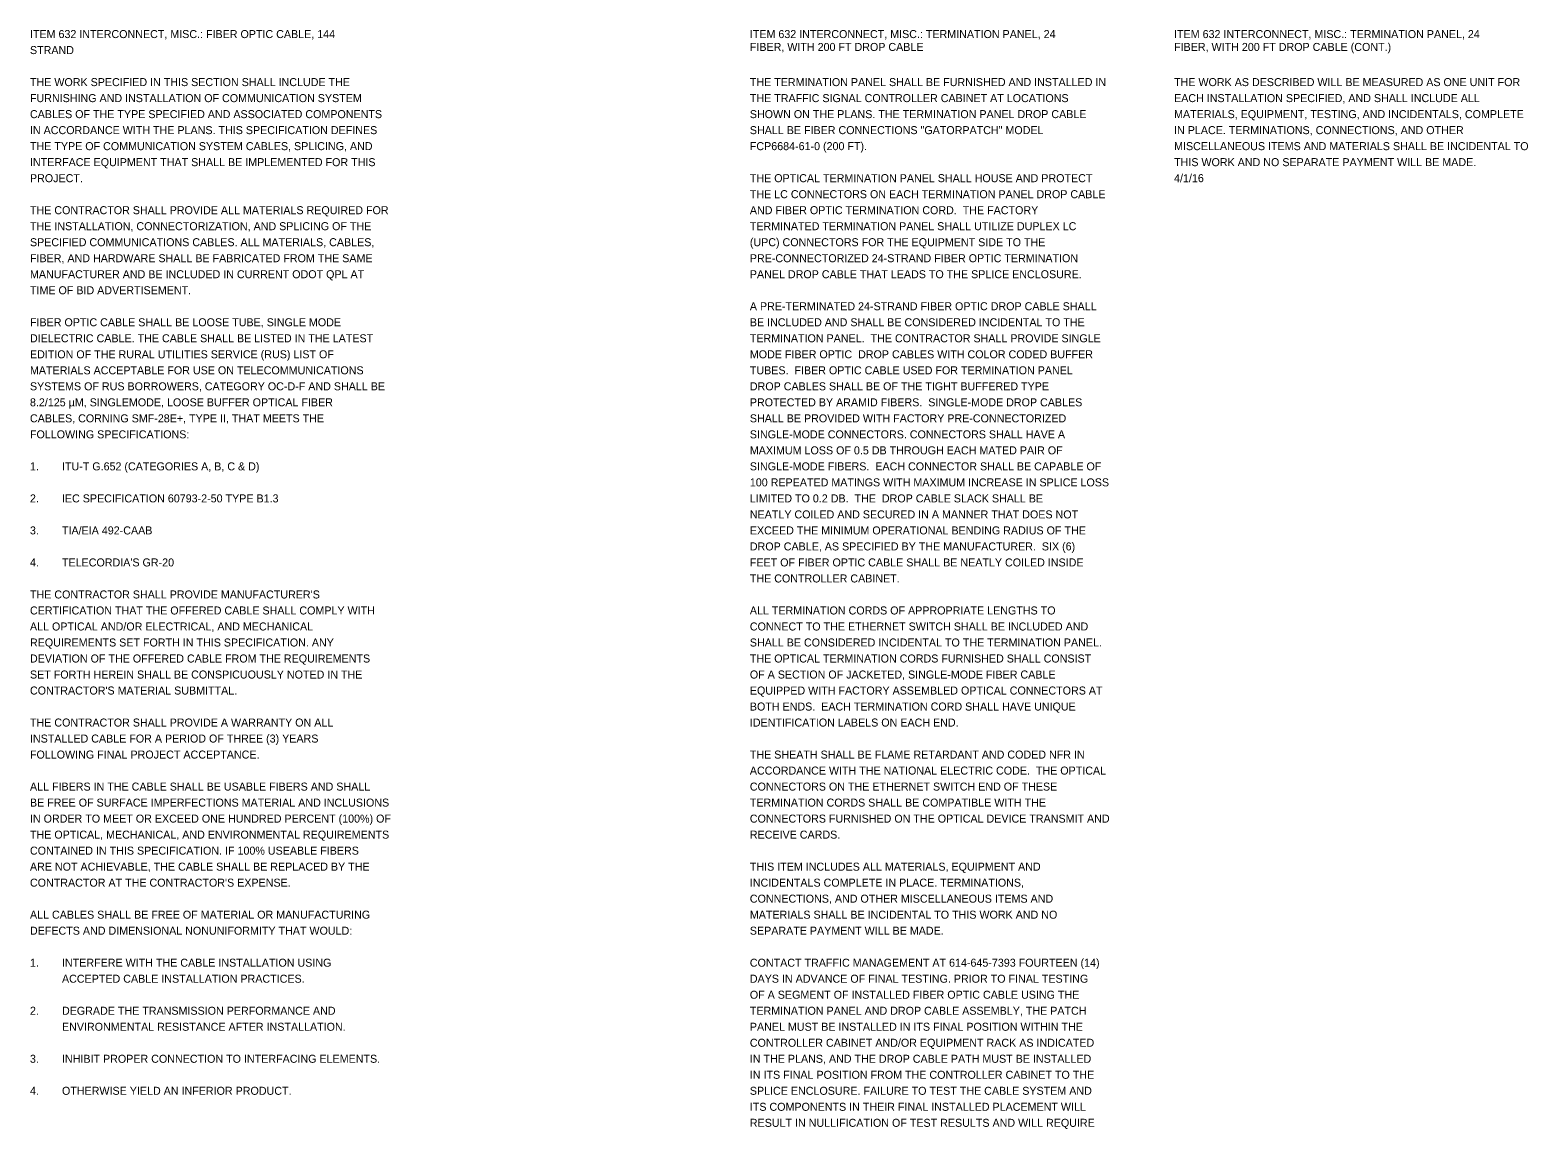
# Model space of a CAD drawing. Extents: x -39 to 75, y -25 to 14.
# Drawn here: x -39.19 to -12.99, y -5.45 to 13.77 of the extents above; entities that cross this region are included whole.
import ezdxf

# ---------------------------------------------------------------- set-up
doc = ezdxf.new("R2010")
doc.units = 0
doc.layers.add('SH_Data', color=7, linetype='Continuous')
doc.layers.add('SH_Text', color=7, linetype='Continuous')

msp = doc.modelspace()

# ---------------------------------------------------------------- texts
at = {"layer": 'SH_Data'}
for s, p in [('ITEM 632 INTERCONNECT, MISC.: FIBER OPTIC CABLE, 144 ', (-39.188, 13.632)), ('ITEM 632 INTERCONNECT, MISC.: TERMINATION PANEL, 24 ', (-26.597, 13.632)), ('ITEM 632 INTERCONNECT, MISC.: TERMINATION PANEL, 24 ', (-19.177, 13.632)), ('STRAND', (-39.188, 13.352)), ('FIBER, WITH 200 FT DROP CABLE', (-26.597, 13.407)), ('FIBER, WITH 200 FT DROP CABLE (CONT.)', (-19.177, 13.407))]:
    msp.add_text(s, height=0.14, dxfattribs=at).set_placement(p)
at = {"layer": 'SH_Text'}
for s, p in [('THE WORK SPECIFIED IN THIS SECTION SHALL INCLUDE THE ', (-39.188, 12.792)), ('FURNISHING AND INSTALLATION OF COMMUNICATION SYSTEM ', (-39.188, 12.512)), ('CABLES OF THE TYPE SPECIFIED AND ASSOCIATED COMPONENTS ', (-39.188, 12.232)), ('IN ACCORDANCE WITH THE PLANS. THIS SPECIFICATION DEFINES ', (-39.188, 11.952)), ('THE TYPE OF COMMUNICATION SYSTEM CABLES, SPLICING, AND ', (-39.188, 11.672)), ('INTERFACE EQUIPMENT THAT SHALL BE IMPLEMENTED FOR THIS ', (-39.188, 11.392)), ('PROJECT.', (-39.188, 11.112)), ('THE CONTRACTOR SHALL PROVIDE ALL MATERIALS REQUIRED FOR ', (-39.188, 10.552)), ('THE INSTALLATION, CONNECTORIZATION, AND SPLICING OF THE ', (-39.188, 10.272)), ('SPECIFIED COMMUNICATIONS CABLES. ALL MATERIALS, CABLES, ', (-39.188, 9.992)), ('FIBER, AND HARDWARE SHALL BE FABRICATED FROM THE SAME ', (-39.188, 9.712)), ('MANUFACTURER AND BE INCLUDED IN CURRENT ODOT QPL AT ', (-39.188, 9.432)), ('TIME OF BID ADVERTISEMENT.', (-39.188, 9.152)), ('FIBER OPTIC CABLE SHALL BE LOOSE TUBE, SINGLE MODE ', (-39.188, 8.592)), ('DIELECTRIC CABLE. THE CABLE SHALL BE LISTED IN THE LATEST ', (-39.188, 8.312)), ('EDITION OF THE RURAL UTILITIES SERVICE (RUS) LIST OF ', (-39.188, 8.032)), ('MATERIALS ACCEPTABLE FOR USE ON TELECOMMUNICATIONS ', (-39.188, 7.752)), ('SYSTEMS OF RUS BORROWERS, CATEGORY OC-D-F AND SHALL BE ', (-39.188, 7.472)), ('8.2/125 µM, SINGLEMODE, LOOSE BUFFER OPTICAL FIBER ', (-39.188, 7.192)), ('CABLES, CORNING SMF-28E+, TYPE II, THAT MEETS THE ', (-39.188, 6.912)), ('FOLLOWING SPECIFICATIONS: ', (-39.188, 6.632)), ('1.', (-39.188, 6.072)), ('ITU-T G.652 (CATEGORIES A, B, C & D)', (-38.628, 6.072)), ('2.', (-39.188, 5.512)), ('IEC SPECIFICATION 60793-2-50 TYPE B1.3', (-38.628, 5.512)), ('3.', (-39.188, 4.952)), ('TIA/EIA 492-CAAB', (-38.628, 4.952)), ('4.', (-39.188, 4.392)), ("TELECORDIA'S GR-20 ", (-38.628, 4.392)), ("THE CONTRACTOR SHALL PROVIDE MANUFACTURER'S ", (-39.188, 3.832)), ('CERTIFICATION THAT THE OFFERED CABLE SHALL COMPLY WITH ', (-39.188, 3.552)), ('ALL OPTICAL AND/OR ELECTRICAL, AND MECHANICAL ', (-39.188, 3.272)), ('REQUIREMENTS SET FORTH IN THIS SPECIFICATION. ANY ', (-39.188, 2.992)), ('DEVIATION OF THE OFFERED CABLE FROM THE REQUIREMENTS ', (-39.188, 2.712)), ('SET FORTH HEREIN SHALL BE CONSPICUOUSLY NOTED IN THE ', (-39.188, 2.432)), ("CONTRACTOR'S MATERIAL SUBMITTAL. ", (-39.188, 2.152)), ('THE CONTRACTOR SHALL PROVIDE A WARRANTY ON ALL ', (-39.188, 1.592)), ('INSTALLED CABLE FOR A PERIOD OF THREE (3) YEARS ', (-39.188, 1.312)), ('FOLLOWING FINAL PROJECT ACCEPTANCE. ', (-39.188, 1.032)), ('ALL FIBERS IN THE CABLE SHALL BE USABLE FIBERS AND SHALL ', (-39.188, 0.472)), ('BE FREE OF SURFACE IMPERFECTIONS MATERIAL AND INCLUSIONS ', (-39.188, 0.192)), ('IN ORDER TO MEET OR EXCEED ONE HUNDRED PERCENT (100%) OF ', (-39.188, -0.088)), ('THE OPTICAL, MECHANICAL, AND ENVIRONMENTAL REQUIREMENTS ', (-39.188, -0.368)), ('CONTAINED IN THIS SPECIFICATION. IF 100% USEABLE FIBERS ', (-39.188, -0.648)), ('ARE NOT ACHIEVABLE, THE CABLE SHALL BE REPLACED BY THE ', (-39.188, -0.928)), ("CONTRACTOR AT THE CONTRACTOR'S EXPENSE.", (-39.188, -1.208)), ('ALL CABLES SHALL BE FREE OF MATERIAL OR MANUFACTURING ', (-39.188, -1.768)), ('DEFECTS AND DIMENSIONAL NONUNIFORMITY THAT WOULD:', (-39.188, -2.048)), ('1.', (-39.188, -2.608)), ('INTERFERE WITH THE CABLE INSTALLATION USING ', (-38.628, -2.608)), ('ACCEPTED CABLE INSTALLATION PRACTICES.', (-38.628, -2.888)), ('2.', (-39.188, -3.448)), ('DEGRADE THE TRANSMISSION PERFORMANCE AND ', (-38.628, -3.448)), ('ENVIRONMENTAL RESISTANCE AFTER INSTALLATION.', (-38.628, -3.728)), ('3.', (-39.188, -4.288)), ('INHIBIT PROPER CONNECTION TO INTERFACING ELEMENTS.', (-38.628, -4.288)), ('4.', (-39.188, -4.848)), ('OTHERWISE YIELD AN INFERIOR PRODUCT. ', (-38.628, -4.848))]:
    msp.add_text(s, height=0.14, rotation=360, dxfattribs=at).set_placement(p)
for s, p in [('THE TERMINATION PANEL SHALL BE FURNISHED AND INSTALLED IN ', (-26.597, 12.792)), ('THE WORK AS DESCRIBED WILL BE MEASURED AS ONE UNIT FOR ', (-19.177, 12.792)), ('THE TRAFFIC SIGNAL CONTROLLER CABINET AT LOCATIONS ', (-26.597, 12.512)), ('EACH INSTALLATION SPECIFIED, AND SHALL INCLUDE ALL ', (-19.177, 12.512)), ('SHOWN ON THE PLANS. THE TERMINATION PANEL DROP CABLE ', (-26.597, 12.232)), ('MATERIALS, EQUIPMENT, TESTING, AND INCIDENTALS, COMPLETE ', (-19.177, 12.232)), ('SHALL BE FIBER CONNECTIONS "GATORPATCH" MODEL ', (-26.597, 11.952)), ('IN PLACE. TERMINATIONS, CONNECTIONS, AND OTHER ', (-19.177, 11.952)), ('FCP6684-61-0 (200 FT).', (-26.597, 11.672)), ('MISCELLANEOUS ITEMS AND MATERIALS SHALL BE INCIDENTAL TO ', (-19.177, 11.672)), ('THIS WORK AND NO SEPARATE PAYMENT WILL BE MADE. ', (-19.177, 11.392)), ('THE OPTICAL TERMINATION PANEL SHALL HOUSE AND PROTECT ', (-26.597, 11.112)), ('4/1/16', (-19.177, 11.112)), ('THE LC CONNECTORS ON EACH TERMINATION PANEL DROP CABLE ', (-26.597, 10.832)), ('AND FIBER OPTIC TERMINATION CORD.  THE FACTORY ', (-26.597, 10.552)), ('TERMINATED TERMINATION PANEL SHALL UTILIZE DUPLEX LC ', (-26.597, 10.272)), ('(UPC) CONNECTORS FOR THE EQUIPMENT SIDE TO THE ', (-26.597, 9.992)), ('PRE-CONNECTORIZED 24-STRAND FIBER OPTIC TERMINATION ', (-26.597, 9.712)), ('PANEL DROP CABLE THAT LEADS TO THE SPLICE ENCLOSURE.', (-26.597, 9.432)), ('A PRE-TERMINATED 24-STRAND FIBER OPTIC DROP CABLE SHALL ', (-26.597, 8.872)), ('BE INCLUDED AND SHALL BE CONSIDERED INCIDENTAL TO THE ', (-26.597, 8.592)), ('TERMINATION PANEL.  THE CONTRACTOR SHALL PROVIDE SINGLE ', (-26.597, 8.312)), ('MODE FIBER OPTIC  DROP CABLES WITH COLOR CODED BUFFER ', (-26.597, 8.032)), ('TUBES.  FIBER OPTIC CABLE USED FOR TERMINATION PANEL ', (-26.597, 7.752)), ('DROP CABLES SHALL BE OF THE TIGHT BUFFERED TYPE ', (-26.597, 7.472)), ('PROTECTED BY ARAMID FIBERS.  SINGLE-MODE DROP CABLES ', (-26.597, 7.192)), ('SHALL BE PROVIDED WITH FACTORY PRE-CONNECTORIZED ', (-26.597, 6.912)), ('SINGLE-MODE CONNECTORS. CONNECTORS SHALL HAVE A ', (-26.597, 6.632)), ('MAXIMUM LOSS OF 0.5 DB THROUGH EACH MATED PAIR OF ', (-26.597, 6.352)), ('SINGLE-MODE FIBERS.  EACH CONNECTOR SHALL BE CAPABLE OF ', (-26.597, 6.072)), ('100 REPEATED MATINGS WITH MAXIMUM INCREASE IN SPLICE LOSS ', (-26.597, 5.792)), ('LIMITED TO 0.2 DB.  THE  DROP CABLE SLACK SHALL BE ', (-26.597, 5.512)), ('NEATLY COILED AND SECURED IN A MANNER THAT DOES NOT ', (-26.597, 5.232)), ('EXCEED THE MINIMUM OPERATIONAL BENDING RADIUS OF THE ', (-26.597, 4.952)), ('DROP CABLE, AS SPECIFIED BY THE MANUFACTURER.  SIX (6) ', (-26.597, 4.672)), ('FEET OF FIBER OPTIC CABLE SHALL BE NEATLY COILED INSIDE ', (-26.597, 4.392)), ('THE CONTROLLER CABINET.', (-26.597, 4.112)), ('ALL TERMINATION CORDS OF APPROPRIATE LENGTHS TO ', (-26.597, 3.552)), ('CONNECT TO THE ETHERNET SWITCH SHALL BE INCLUDED AND ', (-26.597, 3.272)), ('SHALL BE CONSIDERED INCIDENTAL TO THE TERMINATION PANEL.  ', (-26.597, 2.992)), ('THE OPTICAL TERMINATION CORDS FURNISHED SHALL CONSIST ', (-26.597, 2.712)), ('OF A SECTION OF JACKETED, SINGLE-MODE FIBER CABLE ', (-26.597, 2.432)), ('EQUIPPED WITH FACTORY ASSEMBLED OPTICAL CONNECTORS AT ', (-26.597, 2.152)), ('BOTH ENDS.  EACH TERMINATION CORD SHALL HAVE UNIQUE ', (-26.597, 1.872)), ('IDENTIFICATION LABELS ON EACH END.', (-26.597, 1.592)), ('THE SHEATH SHALL BE FLAME RETARDANT AND CODED NFR IN ', (-26.597, 1.032)), ('ACCORDANCE WITH THE NATIONAL ELECTRIC CODE.  THE OPTICAL ', (-26.597, 0.752)), ('CONNECTORS ON THE ETHERNET SWITCH END OF THESE ', (-26.597, 0.472)), ('TERMINATION CORDS SHALL BE COMPATIBLE WITH THE ', (-26.597, 0.192)), ('CONNECTORS FURNISHED ON THE OPTICAL DEVICE TRANSMIT AND ', (-26.597, -0.088)), ('RECEIVE CARDS.', (-26.597, -0.368)), ('THIS ITEM INCLUDES ALL MATERIALS, EQUIPMENT AND ', (-26.597, -0.928)), ('INCIDENTALS COMPLETE IN PLACE. TERMINATIONS, ', (-26.597, -1.208)), ('CONNECTIONS, AND OTHER MISCELLANEOUS ITEMS AND ', (-26.597, -1.488)), ('MATERIALS SHALL BE INCIDENTAL TO THIS WORK AND NO ', (-26.597, -1.768)), ('SEPARATE PAYMENT WILL BE MADE.', (-26.597, -2.048)), ('CONTACT TRAFFIC MANAGEMENT AT 614-645-7393 FOURTEEN (14) ', (-26.597, -2.608)), ('DAYS IN ADVANCE OF FINAL TESTING. PRIOR TO FINAL TESTING ', (-26.597, -2.888)), ('OF A SEGMENT OF INSTALLED FIBER OPTIC CABLE USING THE ', (-26.597, -3.168)), ('TERMINATION PANEL AND DROP CABLE ASSEMBLY, THE PATCH ', (-26.597, -3.448)), ('PANEL MUST BE INSTALLED IN ITS FINAL POSITION WITHIN THE ', (-26.597, -3.728)), ('CONTROLLER CABINET AND/OR EQUIPMENT RACK AS INDICATED ', (-26.597, -4.008)), ('IN THE PLANS, AND THE DROP CABLE PATH MUST BE INSTALLED ', (-26.597, -4.288)), ('IN ITS FINAL POSITION FROM THE CONTROLLER CABINET TO THE ', (-26.597, -4.568)), ('SPLICE ENCLOSURE. FAILURE TO TEST THE CABLE SYSTEM AND ', (-26.597, -4.848)), ('ITS COMPONENTS IN THEIR FINAL INSTALLED PLACEMENT WILL ', (-26.597, -5.128)), ('RESULT IN NULLIFICATION OF TEST RESULTS AND WILL REQUIRE ', (-26.597, -5.408))]:
    msp.add_text(s, height=0.14, dxfattribs=at).set_placement(p)

doc.saveas('drawing.dxf')
